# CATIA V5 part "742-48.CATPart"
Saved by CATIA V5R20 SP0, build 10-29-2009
Part number: 742-48
Bounding box of the stored display mesh (mm): x -40 to 40.5, y -40 to 40, z -47 to 80
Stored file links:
  C:\Users\Utente\Desktop\IO LAVORO\3D X SITO CF\X SITO\742\742-48.CATPart
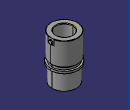
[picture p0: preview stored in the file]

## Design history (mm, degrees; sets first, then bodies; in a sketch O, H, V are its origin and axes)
Set1
  DatumSurface1 to DatumSurface38 "742-48"
Body1 (main body)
